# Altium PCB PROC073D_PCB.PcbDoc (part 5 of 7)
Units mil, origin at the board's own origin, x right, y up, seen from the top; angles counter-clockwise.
Board outline 2165.35 x 2695.12 mil, 8 copper layers (Top Layer, L2_GND, L3_SIGNAL 1, L4_SIGNAL 2, L5_SIGNAL 3, L6_SIGNAL 4, L7_GND, Bottom Layer), stack 56.1 mil thick; 414 components, 319 nets, 1353 pads, 1669 vias.
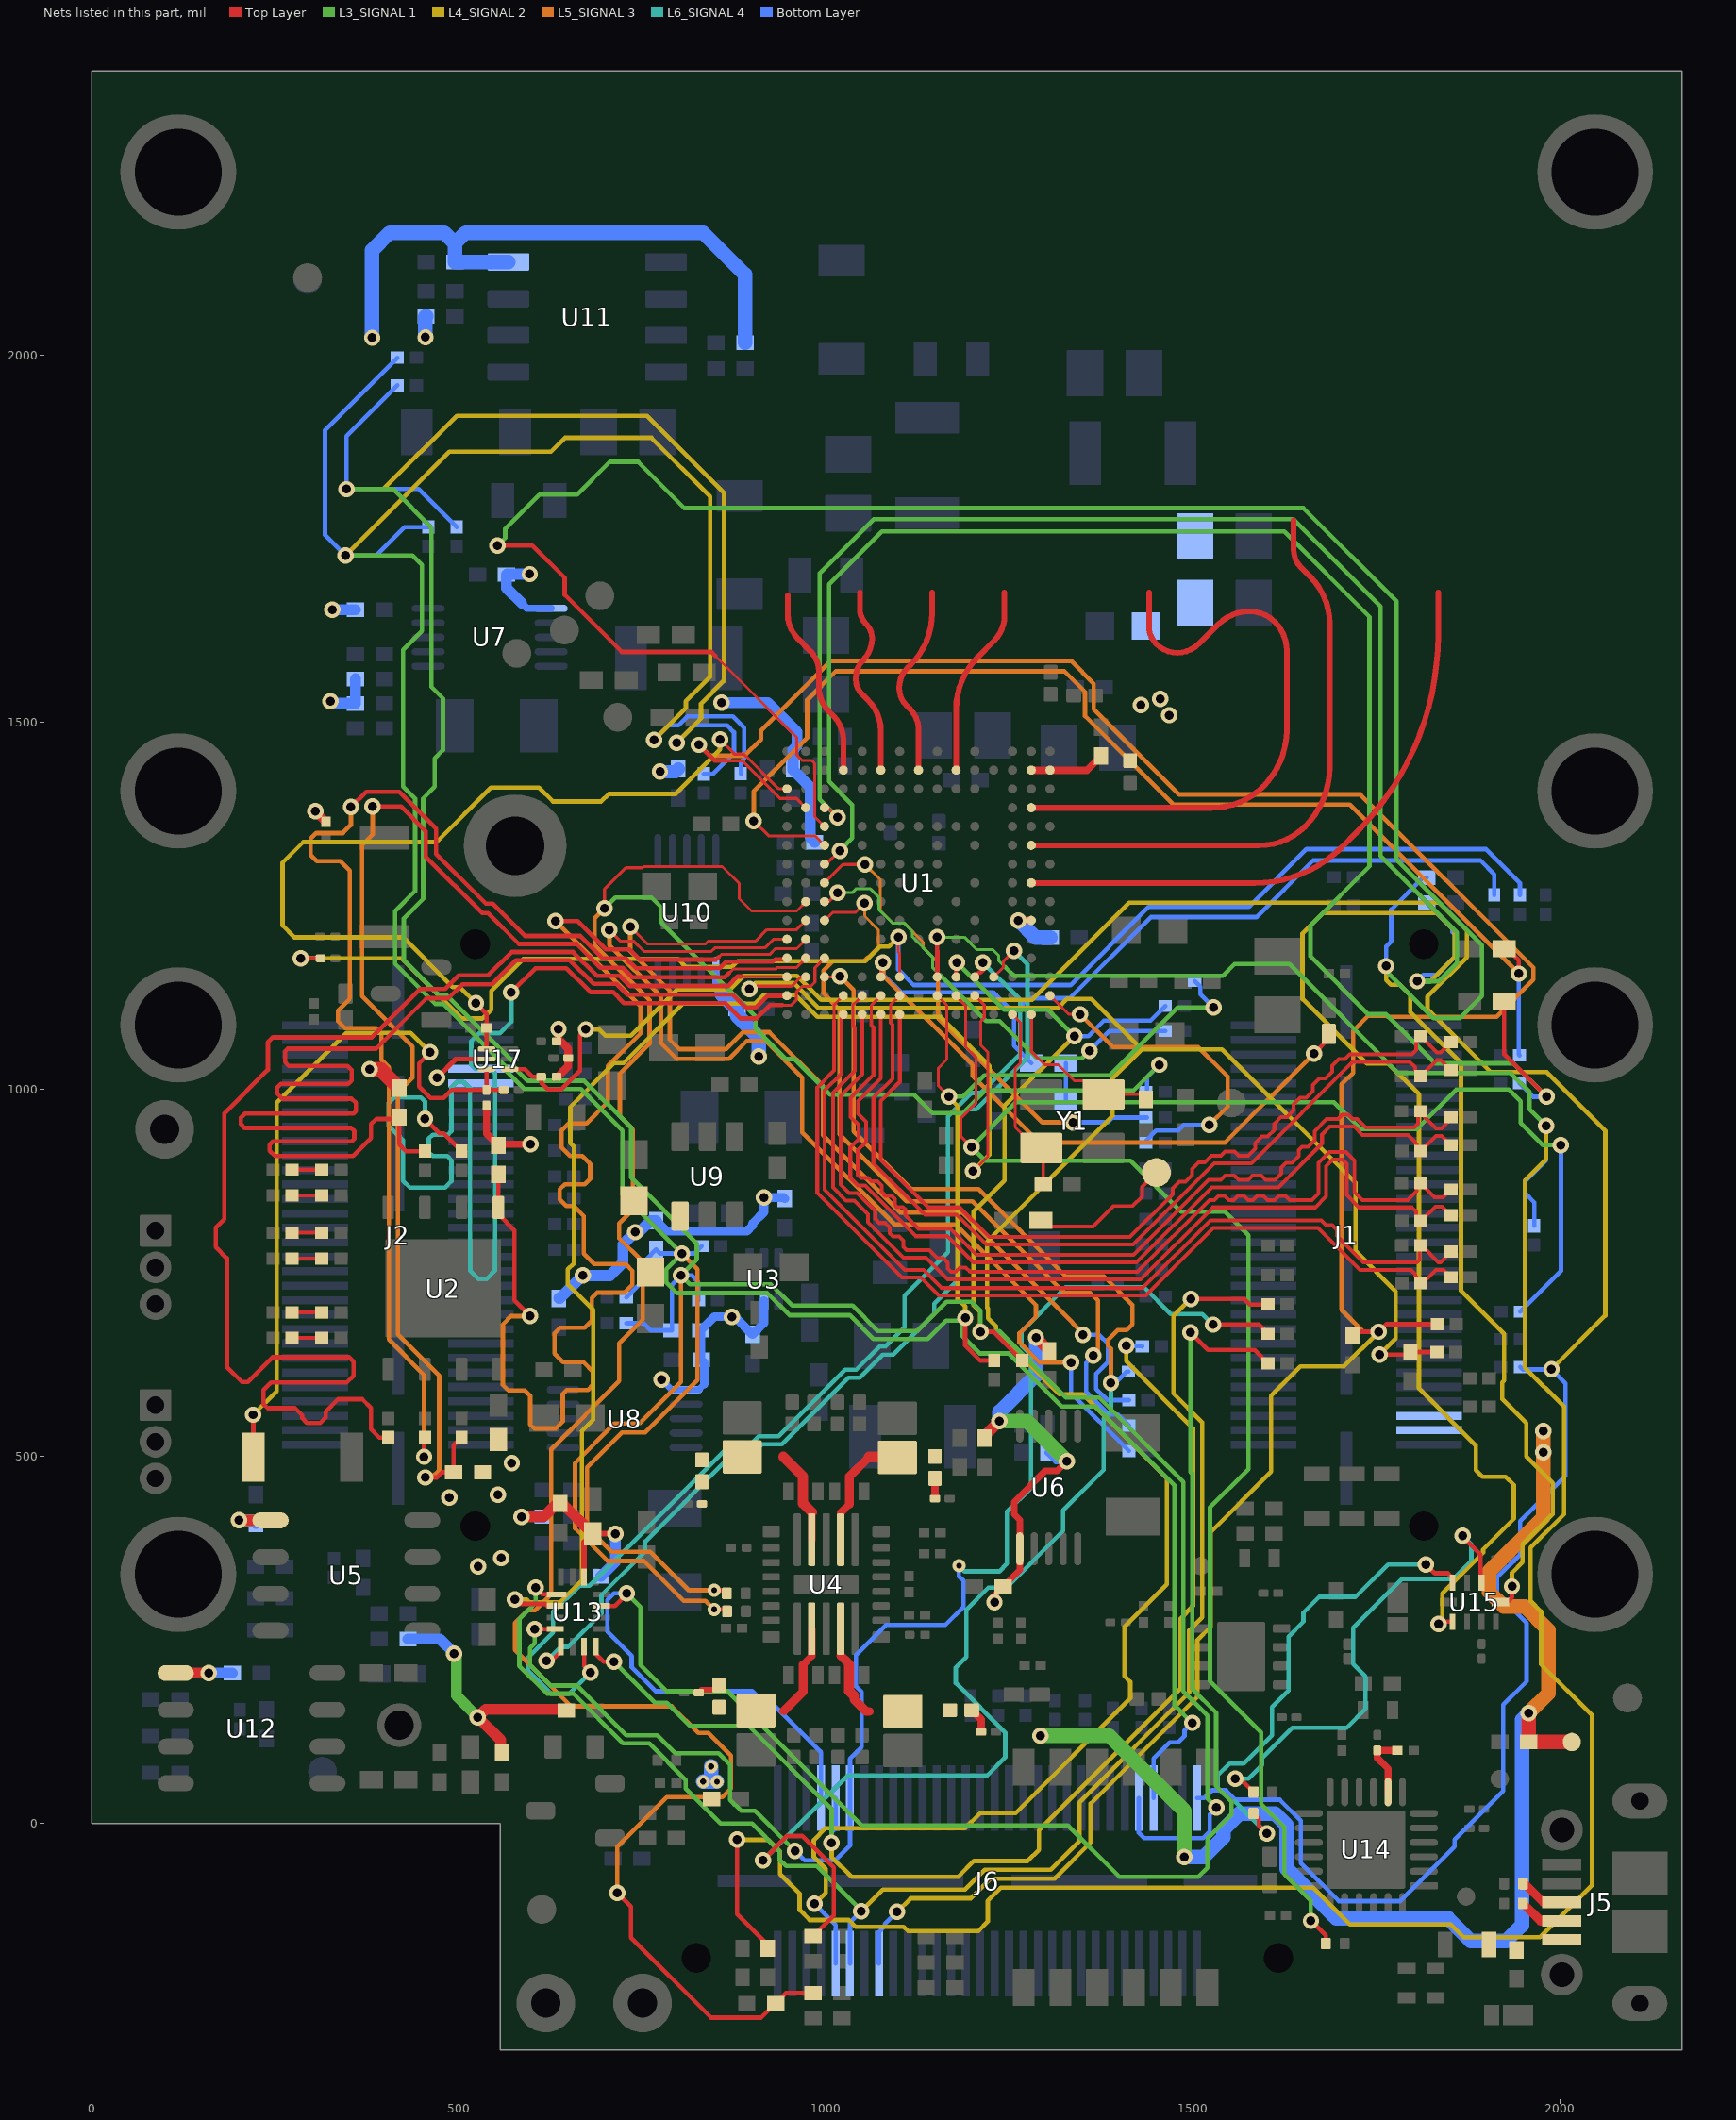
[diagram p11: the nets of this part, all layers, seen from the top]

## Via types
v1: diameter 13.77/15.74 (per signal layer), hole 5.9, Top Layer to L2_GND, tented both sides, 900 vias
v2: diameter 22.4, hole 12.2, Top Layer to Bottom Layer, tented both sides, 509 vias
v3: diameter 13.78/15.75 (per signal layer), hole 5.9, Top Layer to L2_GND, tented both sides, 72 vias
v4: diameter 18, hole 8, Top Layer to Bottom Layer, tented both sides, 71 vias
v5: diameter 22, hole 12.2, Top Layer to Bottom Layer, tented both sides, 57 vias
v6: diameter 25, hole 15, Top Layer to Bottom Layer, tented both sides, 28 vias
v7: diameter 19.68, hole 7.87, Top Layer to Bottom Layer, 16 vias
v8: diameter 13.77/15.74 (per signal layer), hole 5.9, Top Layer to L2_GND, tented top, 15 vias
v9: diameter 13.78/15.75 (per signal layer), hole 5.9, Top Layer to L2_GND, tented top, 1 vias

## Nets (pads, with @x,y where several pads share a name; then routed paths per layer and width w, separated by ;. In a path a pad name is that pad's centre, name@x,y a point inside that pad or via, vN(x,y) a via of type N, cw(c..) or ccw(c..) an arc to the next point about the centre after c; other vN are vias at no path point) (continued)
RADAR_GPIO_1: R66.2 R214.2 U1.J13 | length 2010.4
  Top Layer w4: v2(1098.42,1207.09) 1098.42,1186.89 1100.38,1184.93 U1.J13@1100.39,1153.09
  Top Layer w6: v2(284.89,1178.31) R214.2@311.88,1178.31
  L4_SIGNAL 2 w6: v2(284.89,1178.31) 422.38,1178.31 504.39,1096.29 531.99,1096.29 544.12,1108.41 544.12,1133.77 587.78,1177.43 798.52,1177.43 809.15,1166.81 871.95,1166.81 879.77,1174.63 1053.7,1174.63 1073.32,1194.26 1085.59,1194.26 v2(1098.42,1207.09)
  Bottom Layer w6: v2(1098.42,1207.09) 1098.42,1163 1119.53,1141.9 1332.85,1141.9 1439.38,1248.43 1575.75,1248.43 1654.41,1327.09 1898.61,1327.09 1945,1280.7 R66.2@1945,1264.42
RADAR_GPIO_2: D7.1 R67.2 R185.2 U1.K13 | length 1892.2
  Top Layer w4: U1.K13@1074.8,1153.09 1074.79,1169.37 v2(1077.67,1172.25)
  Top Layer w6: v5(1664.57,1048.61) 1684.74,1068.78 D7.1@1684.74,1075.28
  L5_SIGNAL 3 w6: v2(1077.67,1172.25) 1077.67,1155.22 1199.32,1033.57 1199.32,1018.6 1290.49,927.43 1543.4,927.43 v5(1664.57,1048.61)
  Bottom Layer w6: v2(1077.67,1172.25) 1077.67,1156.76 1102.53,1131.9 1227.96,1131.9 1251.05,1108.8 ; R185.2@1279.5,1035.79 1256,1059.29 1256,1103.86 ; R67.2@1910,1264.42 1910,1292.73 1891.13,1311.6 1663.14,1311.6 1585.97,1234.43 1442.35,1234.43 1331.94,1124.02 1276.17,1124.02 1260.95,1108.8 ; 1251.05,1108.8 1256,1103.86 ; 1251.05,1108.8 1260.95,1108.8 ; 1256,1103.86 1260.95,1108.8
RADAR_HOSTINTR1: J6.10 R10.2 R152.2 U1.P13 | length 3214.1
  Top Layer w4: v2(895.59,1136.43) 899.55,1140.38 953.35,1140.38 965.85,1152.88 U1.P13@972.64,1152.88
  Top Layer w6: v2(1754.07,638.82) 1792.52,638.82 R152.2@1795.94,642.24 R10.2@1831.68,642.24
  L4_SIGNAL 2 w6: v2(895.59,1136.43) 903.79,1144.63 956.23,1144.63 990.39,1110.47 1315.6,1110.47 1328.02,1122.9 1361.41,1122.9 1424.28,1060.03 ; v2(984.35,-109.22) 999.65,-93.92 999.65,-61.63 983.46,-45.44 983.46,-22.05 999.35,-6.16 1189.38,-6.16 1210.26,14.72 1258.62,14.72 1414.33,170.42 1414.33,193.22 1406.72,200.83 1406.72,268.62 1464.29,326.19 1464.29,470.5 1349.84,584.95 1317.77,584.95 1231.45,671.27 1231.45,677.52 1220.64,688.34 1220.64,701.39 1219.49,702.54 1219.49,792.59 1390.36,963.47 1390.36,1014.89 1424.28,1048.81 ; v2(1754.07,638.82) 1775.89,660.63 1775.89,724.97 1721.01,779.85 1721.01,872.87 1539.46,1054.42 1429.89,1054.42 ; 1424.28,1048.81 1429.89,1054.42 ; 1424.28,1048.81 1424.28,1060.03 ; 1424.28,1060.03 1429.89,1054.42
  Bottom Layer w6: v2(984.35,-109.22) 1013.05,-137.91 J6.10@1013.05,-190.65
RADAR_INTn: R184.1 R185.1 | length 51.8
  Bottom Layer w6: R184.1@1326.74,984.02 R185.1@1326.74,1035.79
RADAR_LVDS_0M: R41.2 R230.2 U1.J15 | length 1202.8
  Top Layer w5.2: U1.J15@1100.59,1101.7 1100.59,1010 1074.79,984.2 1074.79,903.5 1139.16,839.13 1182.09,839.13 1222.49,798.73 1413.97,798.73 1472.09,856.85 1472.09,865.1 1481.04,874.06 1489.3,874.06 1498.36,883.12 1498.36,891.38 1507.31,900.33 1515.57,900.33 1524.63,909.39 1537.76,909.39 1543.6,915.23 1556.26,915.23 1562.1,909.39 1574.91,909.39 1584.35,918.82 1584.35,927.08 1593.3,936.03 1601.56,936.03 1610.62,945.1 1610.62,953.35 1619.57,962.3 1627.83,962.3 1636.89,971.37 1636.89,979.62 1645.84,988.58 1654.1,988.58 1663.16,997.64 1663.16,1005.89 1672.11,1014.85 1680.37,1014.85 1689.43,1023.91 1689.43,1032.16 1698.38,1041.12 1706.64,1041.12 1712.84,1047.32 1797.57,1047.32 1803.41,1053.16 1803.41,1065.93 R230.2@1809.84,1072.37 1810.22,1071.98 1832.03,1050.18 1836.91,1050.18 R41.2@1850.8,1064.07
RADAR_LVDS_0P: R39.2 R229.2 U1.J14 | length 1205.6
  Top Layer w4: 1087.88,1094.5 1087.88,1115.01 U1.J14@1100.39,1127.5
  Top Layer w5.2: 1087.88,1094.5 1087.88,1090.49 1090.39,1087.98 1090.39,1014.23 1064.59,988.43 1064.59,899.28 1134.93,828.93 1177.87,828.93 1218.27,788.53 1418.2,788.53 1528.85,899.19 1579.14,899.19 1717.07,1037.12 1794.88,1037.12 1802.06,1029.94 1802.06,1025.66 R229.2@1809.84,1017.88 R229.2@1810.22,1018.26 ; R229.2@1810.26,1018.22 R229.2@1810.22,1018.26 ; R39.2@1850.8,1026.09 1836.91,1039.98 1831.94,1039.98 R229.2@1810.22,1018.26
RADAR_LVDS_1M: R35.2 R228.2 U1.K15 | length 1256
  Top Layer w5.2: U1.K15@1074.8,1101.91 1074.79,1015.13 1043.72,984.06 1043.72,966.45 1054.39,955.79 1054.39,928 1043.35,916.96 1043.35,883.39 1047.68,879.07 1057.31,879.07 1061.69,874.68 1069.95,874.68 1075.8,868.83 1075.8,860.58 1081.18,855.19 1089.44,855.19 1093.96,850.67 1093.96,842.41 1096.69,839.69 1104.94,839.69 1108.01,836.62 1108.01,828.37 1126.21,810.16 1169.48,810.16 1205.01,774.63 1418.72,774.63 1520.99,876.9 1537.51,876.9 1543.35,882.74 1556.01,882.74 1561.84,876.9 1574.66,876.9 1580.5,882.74 1593.16,882.74 1599,876.9 1611.81,876.9 1619.9,884.99 1619.9,893.24 1626.27,899.62 1634.53,899.62 1643.59,908.68 1643.59,916.93 1648.44,921.79 1656.7,921.79 1665.28,930.37 1665.28,942.71 1681.86,959.29 1697.24,959.29 1703.07,965.13 1711.34,965.13 1717.18,959.29 1723.39,959.29 1734.65,948.03 1801.03,948.03 1805.97,952.97 1805.97,966.31 R228.2@1809.84,970.18 1809.84,967.34 1830.33,946.85 1838.34,946.85 1850.8,959.31 R35.2@1850.8,961.88
RADAR_LVDS_1P: R33.2 R227.2 U1.K14 | length 1255.6
  Top Layer w4: 1061.87,1094.5 1061.87,1114.59 U1.K14@1074.8,1127.5
  Top Layer w5.2: 1061.87,1094.5 1061.87,1087.2 1064.59,1084.48 1064.59,1019.35 1033.52,988.28 1033.52,962.23 1044.19,951.56 1044.19,932.23 1033.15,921.19 1033.15,879.17 1043.45,868.87 1053.08,868.87 1121.98,799.96 1165.25,799.96 1200.79,764.43 1422.94,764.43 1525.22,866.7 1616.04,866.7 1675.48,926.14 1675.48,938.48 1686.09,949.09 1719.16,949.09 1730.43,937.83 1792.75,937.83 1802.48,928.09 1802.48,926.6 1805.16,923.92 1805.16,921.14 R227.2@1810.26,916.04 1830.88,936.65 1838.05,936.65 R33.2@1850.8,923.9
RADAR_LVDS_2M: R137.2 R224.2 | length 40.6
  Top Layer w5.2: R137.2@272.99,661.43 R224.2@313.6,661.43
RADAR_LVDS_2P: R136.2 R223.2 | length 40.6
  Top Layer w5.2: R136.2@272.99,696.43 R223.2@313.6,696.43
RADAR_LVDS_3M: R135.2 R222.2 | length 40.6
  Top Layer w5.2: R135.2@272.99,769.68 R222.2@313.6,769.68
RADAR_LVDS_3P: R134.2 R221.2 | length 40.6
  Top Layer w5.2: R134.2@272.99,804.68 R221.2@313.6,804.68
RADAR_LVDS_CLKM: R32.2 R226.2 U1.L15 | length 1337.3
  Top Layer w5.2: U1.L15@1049.41,1101.7 1049.41,1084.28 1049.4,1020.66 1019.78,991.04 1019.78,870.45 1031.58,858.65 1042.55,858.65 1067.21,833.99 1067.21,823.32 1072.61,817.93 1080.86,817.93 1086.71,812.08 1086.71,803.82 1091.1,799.44 1099.35,799.44 1105.2,793.59 1105.2,785.33 1109.59,780.95 1140.54,780.95 1151.67,769.82 1159.93,769.82 1165.77,763.97 1165.77,755.72 1170.16,751.33 1176.36,751.33 1182.2,757.17 1190.47,757.17 1196.31,751.33 1424.27,751.33 1522.26,849.32 1528.8,849.32 1534.64,855.16 1542.91,855.16 1548.75,849.32 1554.95,849.32 1560.79,855.16 1569.06,855.16 1574.89,849.32 1581.1,849.32 1586.94,855.16 1595.61,855.16 1601.45,849.32 1610.84,849.32 1616.68,855.16 1625.64,855.16 1631.48,849.32 1661.78,849.32 1670.6,858.14 1670.6,899.79 1685.54,914.73 1707.71,914.73 1719.51,902.93 1719.51,860.24 1730.42,849.32 1792.01,849.32 1804.09,861.4 1804.09,866.09 R226.2@1809.84,871.84 1828.71,852.97 1840.22,852.97 R32.2@1850.8,863.55
RADAR_LVDS_CLKP: R30.2 R225.2 U1.L14 | length 1347.6
  Top Layer w4: 1036.49,1094.28 1036.49,1114.37 U1.L14@1049.41,1127.29
  Top Layer w5.2: 1036.49,1094.28 1036.49,1086.98 1039.2,1084.27 1039.2,1024.89 1009.58,995.27 1009.58,866.22 1027.35,848.45 1038.33,848.45 1057.01,829.77 1057.01,819.1 1105.36,770.75 1136.32,770.75 1165.93,741.13 1428.49,741.13 1526.49,839.12 1666,839.12 1680.8,853.92 1680.8,895.57 1689.76,904.53 1703.48,904.53 1709.31,898.71 1709.31,856.01 1726.2,839.12 1798.1,839.12 1803.63,833.6 1803.63,827.32 R225.2@1810.26,820.68 1829.86,840.29 1839.06,840.29 R30.2@1850.8,828.55
RADAR_LVDS_FRCLKM: R24.2 R220.2 U1.M15 | length 1259.6
  Top Layer w5.2: U1.M15@1023.82,1101.7 1021.27,1099.16 1021.27,1021.39 998.4,998.51 998.4,862.98 1107.5,753.88 1133.19,753.88 1157.74,729.32 1431.11,729.32 1523.33,821.55 1674.32,821.55 1680.96,814.91 1689.21,814.91 1695.55,808.57 1695.55,800.31 1731.42,764.45 1804.95,764.45 1808.29,767.79 1808.29,785.14 R220.2@1809.84,786.69 ; R220.2@1809.84,787.38 R220.2@1809.84,786.69 ; R24.2@1850.8,779.08 1850.8,778.24 1836.91,764.36 1834.02,764.36 1811.69,786.69 R220.2@1809.84,786.69
RADAR_LVDS_FRCLKP: R22.2 R219.2 U1.M14 | length 1287.2
  Top Layer w4: 1011.07,1093.13 1011.07,1114.96 U1.M14@1023.62,1127.5
  Top Layer w5.2: 1011.07,1093.13 1011.07,1025.61 988.2,1002.74 988.2,858.75 1103.27,743.68 1128.96,743.68 1153.52,719.12 1435.34,719.12 1527.56,811.35 1670.09,811.35 1727.19,754.25 1796.51,754.25 1802.48,748.27 1802.48,746.55 1810.26,738.77 R219.2@1810.26,736.22 1812.79,736.22 1830.59,754.02 1840.86,754.02 R22.2@1850.8,744.08
RADAR_LVDS_VALIDM: R133.2 R218.2 | length 40.6
  Top Layer w5.2: R133.2@272.99,855.5 R218.2@313.6,855.5
RADAR_LVDS_VALIDP: R131.2 R217.2 | length 40.6
  Top Layer w5.2: R131.2@272.99,890.5 R217.2@313.6,890.5
RADAR_MCUCLKOUT: R62.2 U1.N8 | length 671
  Top Layer w4: U1.N8@998.03,1281.05 1007.57,1290.6 1007.57,1290.66 1023.06,1306.15 v2(1053.07,1306.15)
  L5_SIGNAL 3 w4: v2(1053.07,1306.15) 1073.87,1285.35 1073.87,1242.99 1090.58,1226.29 1106.38,1226.29 1132.27,1200.39 1132.27,1193.04 1152.74,1172.57 1152.74,1145.5
  L5_SIGNAL 3 w6: 1152.74,1145.5 1152.74,1096.88 1294.64,954.98 v2(1336.33,954.98)
  Bottom Layer w6: v2(1336.33,954.98) 1383.35,954.98 1389.8,961.43 R62.2@1437.01,961.43
RADAR_MISO1: U1.E14 U13.2 | length 1919.6
  Top Layer w4: v2(1200,888.33) 1220.53,908.87 1220.53,1050.18 1210.95,1059.77 1210.95,1092.72 1215.5,1097.27 1215.5,1114.75 U1.E14@1202.95,1127.29
  Top Layer w6: v2(576.47,305.17) 582.4,299.24 617.96,299.24 620.72,296.48 U13.2@631.29,296.48
  L4_SIGNAL 2 w6: v2(576.47,305.17) 592.29,305.17 596.31,301.15 637.64,301.15 667.49,331 667.49,534.39 682.92,549.81 682.92,699.78 648.54,734.16 648.54,754.79 656.57,762.82 656.57,921.99 651.9,926.66 651.9,976 711.53,1035.63 724.5,1035.63 805.38,1116.5 903.48,1116.5 915.54,1128.56 958.16,1128.56 988.27,1098.44 1156.04,1098.44 1222.47,1032.01 1222.47,910.8 v2(1200,888.33)
RADAR_MOSI1: U1.D13 U13.5 | length 1385
  Top Layer w4: U1.D13@1228.54,1152.88 1241.43,1165.77 1241.43,1173.95 v2(1256.07,1188.6)
  Top Layer w6: v2(619.68,221.88) 626.25,221.88 639.17,234.8 U13.5@639.17,241.36
  L6_SIGNAL 4 w6: v2(619.68,221.88) 620.08,221.88 639.05,240.85 649.15,240.85 694.33,286.03 694.33,311.44 753.44,370.55 753.44,383.98 875.11,505.66 902.23,505.66 913.27,516.7 940.05,516.7 1030.65,607.29 1045.73,607.29 1077.28,638.84 1091.86,638.84 1147.64,694.62 1147.64,707.98 1179.75,740.09 1179.75,958.32 1194.05,972.63 1204.38,972.63 1274.23,1042.48 1274.23,1170.44 v2(1256.07,1188.6)
RADAR_MSS_LOGGER: R31.2 R96.2 U1.F14 | length 2874.4
  Top Layer w4: U1.F14@1177.16,1127.5 1177.15,1126.82 1189.87,1114.1 ; 1190.28,1113.69 1190.28,1057.78 1204.53,1043.53 1204.53,981.7 1183.59,960.75 1183.59,935.92 v2(1197.95,921.56)
  Top Layer w6: v5(1660.15,-132.27) 1660.79,-132.27 1680.69,-152.17 R96.2@1680.69,-163.08
  L3_SIGNAL 1 w6: v5(1660.15,-132.27) 1660.15,-104.5 1623.96,-68.31 1623.96,-4.54 1592.78,26.63 1592.78,124.13 1522.81,194.11 1522.81,430.34 1575.37,482.9 1575.37,801.44 1543.35,833.46 1483.64,833.46 1414.43,902.68 1216.83,902.68 v2(1197.95,921.56) 1258.78,982.39 1691.76,982.39 1728.06,946.09 1804.48,946.09 1858.29,999.91 1929.75,999.91 1946.07,983.59 1946.07,954.12 1976.13,924.06 v2(2000.74,924.06)
  Bottom Layer w6: R31.2@1945.35,697.17 2000.74,752.55 v2(2000.74,924.06)
RADAR_NERR_OUT: R59.2 R169.1 U1.N6 | length 1636.3
  Top Layer w4: v2(901.68,1365.29) 921.88,1345.09 985.16,1345.09 U1.N6@998.23,1332.02
  Top Layer w6: R169.1@1923.62,1191.43 1927.84,1191.43 1943.4,1175.87 v5(1943.4,1157.46)
  L5_SIGNAL 3 w6: v2(901.68,1365.29) 901.68,1405.88 974.47,1478.67 974.47,1530.15 1013.56,1569.25 1324.43,1569.25 1352.77,1540.9 1352.77,1508.13 1473.37,1387.54 1713.33,1387.54 v5(1943.4,1157.46)
  Bottom Layer w6: v5(1943.4,1157.46) 1943.4,1047.24 R59.2@1944.29,1046.36
RADAR_NERRIN: R58.2 R150.1 U1.N7 | length 2319.6
  Top Layer w4: U1.N7@998.03,1306.64 1000.46,1306.64 v2(1018.77,1324.95)
  Top Layer w6: R150.1@1923.62,1119.34 1923.62,1047.64 v2(1981.41,989.85)
  L3_SIGNAL 1 w6: v2(1018.77,1324.95) 1035.84,1342.02 1035.84,1387.27 1004.12,1419 1004.12,1687.54 1076,1759.43 1624,1759.43 1740,1643.43 1740,1303.41 1659.8,1223.21 1659.8,1180.72 1738.4,1102.12 1762.63,1102.12 1829.43,1035.32 1935.94,1035.32 v2(1981.41,989.85)
  Bottom Layer w6: R58.2@1944.29,1008.12 1962.57,989.84 ; 1962.58,989.85 v2(1981.41,989.85)
RADAR_NRST: R171.1 U1.R3 U17.4 | length 1268.6
  Top Layer w4: v2(855.59,1476.43) 875.59,1456.43 888.22,1456.43 935.65,1409 U1.R3@946.84,1409
  Top Layer w6: v2(523.42,1116.99) 537.82,1102.59 R171.1@537.82,1083.65 U17.4@537.82,1054.92
  L4_SIGNAL 2 w6: v2(523.42,1116.99) 501.1,1139.31 491.8,1139.31 424.14,1206.97 276.09,1206.97 260.09,1222.97 260.09,1308.41 288.33,1336.65 469.57,1336.65 543.71,1410.78 609.32,1410.78 628.16,1391.94 694.15,1391.94 704.29,1402.07 794.82,1402.07 855.59,1462.85 v2(855.59,1476.43)
RADAR_NRST_1: J6.59 R42.1 R123.2 U17.1 | length 3578
  Top Layer w6: U17.1@569.32,1027.36 590,1027.36 600.37,1016.99 R123.2@612.21,1016.99 612.21,1008.96 621.65,999.52 639.36,999.52 665,1025.16 665,1073.71 v5(672.99,1081.7)
  L4_SIGNAL 2 w6: v5(672.99,1081.7) 690.74,1081.7 699.62,1072.82 734.38,1072.82 797.6,1136.05 869.47,1136.05 888.05,1154.63 960.37,1154.63 993.19,1121.81 1280.71,1121.81 1412.8,1253.91 1834.46,1253.91 1872.52,1215.84 1872.52,1179.54 1819,1126.02 1819,1109.66 1905.14,1023.53 1981.47,1023.53 2061.12,943.88 2061.12,691.76 v2(1987.95,618.6)
  Bottom Layer w6: J6.59@1505.17,34.94 1514.99,34.94 1525.53,45.48 1544.77,45.48 1557.54,32.71 1617.9,32.71 1646.38,4.23 1646.38,-53.44 1698.3,-105.37 1782.08,-105.37 1856.09,-31.36 1856.09,-21.52 1922.29,44.68 1922.29,162.2 1954.02,193.93 1954.02,273.02 1913.85,313.19 1913.85,335.37 1945.07,366.59 1945.07,411.96 2006.94,473.83 2006.94,599.61 v2(1987.95,618.6) 1948.7,618.6 R42.1@1945.37,621.93
RADAR_NRST_2: C53.1 R165.1 S2.1 U17.6 | length 962.8
  Top Layer w6: S2.1@220.18,498.89 v2(220.18,556.83) ; v2(461.07,1050.23) 446.22,1035.38 446.22,1003.62 461.66,988.18 479.22,988.18 490.14,999.1 R165.1@537.82,999.1 ; U17.6@537.82,1027.36 R165.1@537.82,999.1 ; C53.1@561.55,999.1 R165.1@537.82,999.1
  L4_SIGNAL 2 w6: v2(220.18,556.83) 251.88,588.53 251.88,981.68 346.95,1076.75 434.55,1076.75 v2(461.07,1050.23)
RADAR_OSC_CLKOUT: R61.2 U1.A14 | length 461.2
  Top Layer w4: U1.A14@1305.31,1127.29 1330.44,1102.17 v2(1346,1102.17)
  L5_SIGNAL 3 w6: v2(1346,1102.17) 1390.71,1057.46 1506.77,1057.46 1546.85,1017.38 1546.85,976.28 v2(1522,951.43)
  Bottom Layer w6: R61.2@1435.75,927.14 1435.75,929.85 1449.6,943.7 1479.36,943.7 1487.09,951.43 v2(1522,951.43)
RADAR_PMIC_CLKOUT_SOP2: R63.2 R202.1 R203.1 U1.P9 | length 3525.3
  Top Layer w4: v2(698.56,1246.63) 698.56,1272.61 727.54,1301.6 750.26,1301.6 751.95,1303.29 858.73,1303.29 881.8,1280.22 881.8,1259.55 898.6,1242.75 960.14,1242.75 U1.P9@972.64,1255.25
  Top Layer w6: v2(715.89,-94.12) 734.49,-112.71 734.49,-155.18 843.39,-264.08 911.78,-264.08 R202.1@931.56,-244.3 945.14,-230.73 R203.1@982.36,-230.73
  L3_SIGNAL 1 w6: v2(698.56,1246.63) 713.21,1261.29 762.43,1261.29 776.38,1247.34 776.38,1226.72 904.09,1099.01 904.09,1082.75 945.79,1041.04 957.3,1041.04 1005.57,992.77 1119.89,992.77 1144.9,967.76 1186.5,967.76 1216.88,998.13 1418.44,998.13 v2(1453.74,1033.43)
  L5_SIGNAL 3 w6: v2(698.56,1246.63) 684.97,1233.05 684.97,1196.39 759.72,1121.64 759.72,1061.76 719.42,1021.46 719.42,962.94 737.21,945.15 737.21,836.11 718.55,817.45 718.55,797.06 750.54,765.07 750.54,686.22 718.55,654.22 718.55,602.63 625.82,509.9 625.82,312.59 603.99,290.77 593.96,290.77 576.37,273.17 576.37,236.62 653.19,159.8 789.97,159.8 826.27,123.49 839.98,123.49 870.55,92.92 870.55,47.66 859.27,36.38 783.22,36.38 715.89,-30.95 v2(715.89,-94.12)
  Bottom Layer w6: R63.2@1437.01,996.43 1437.01,1016.7 v2(1453.74,1033.43)
RADAR_QSPI_CS: R50.2 U1.P11 U2.1 | length 1918.3
  Top Layer w4: 853.78,1179.99 857.41,1183.63 923.26,1183.63 931.06,1191.43 960.31,1191.43 U1.P11@972.34,1203.45
  Top Layer w6: R50.2@553.88,884.16 U2.1@553.88,839.09 553.88,829.86 575.82,807.92 575.82,712.58 v2(597.22,691.17) ; v2(631.53,1229.05) 661.97,1229.05 700.59,1190.43 732.63,1190.43 746.28,1176.77 850.55,1176.77 853.78,1179.99
  L5_SIGNAL 3 w6: v2(597.22,691.17) 571.49,691.17 560.03,679.71 560.03,597.72 567.78,589.97 590.05,589.97 597.22,582.8 597.22,543.66 602.57,538.31 632.52,538.31 641.56,547.35 641.56,585.12 647.13,590.68 676.01,590.68 682.71,597.37 682.71,615.51 669.88,628.33 641.99,628.33 630.43,639.89 630.43,667.69 638.14,675.4 671.61,675.4 681.15,684.93 681.15,715.88 688.56,723.3 726.17,723.3 736.44,733.57 736.44,752.77 727.37,761.85 684.47,761.85 670.19,776.12 670.19,827.23 656.47,840.95 646.73,840.95 637.64,850.05 637.64,863.87 644.34,870.57 671.47,870.57 678.98,878.08 678.98,898.42 668.28,909.12 651.58,909.12 639.81,920.88 639.81,943.91 649.48,953.57 673.9,953.57 703,982.67 703,1031.73 747.72,1076.45 747.72,1112.86 v2(631.53,1229.05)
RADAR_QSPI_D0: R45.2 U1.R13 | length 1866
  Top Layer w4: 884.59,1153.63 946.3,1153.63 U1.R13@947.05,1152.88
  Top Layer w6: R45.2@403.88,525.86 391.76,525.86 380.57,537.05 380.57,566.08 368.63,578.03 335.75,578.03 318.83,561.11 318.83,553.03 311.46,545.65 293.36,545.65 286.6,552.41 286.6,556.2 276.96,565.85 239.73,565.85 234.22,571.35 234.22,590.7 244.21,600.69 347.44,600.69 356.65,609.9 356.65,629.2 350.59,635.26 246.66,635.26 212.98,601.58 204.86,601.58 184.2,622.23 184.2,770 169.02,785.18 169.02,811.47 180.88,823.33 180.88,967.19 240.1,1026.41 240.1,1064.12 246.71,1070.74 381.54,1070.74 447.24,1136.44 481.53,1136.44 500.21,1155.12 540.01,1155.12 571.74,1186.85 655.7,1186.85 688.12,1154.43 719.13,1154.43 732.93,1140.63 866.71,1140.63 879.71,1153.63 884.59,1153.63
RADAR_QSPI_D1: R46.1 U1.N12 | length 1798.5
  Top Layer w4: 940.59,1114.5 952.87,1114.5 959.37,1121 959.37,1132.2 967.27,1140.1 979.17,1140.1 984.97,1145.9 984.97,1165.64 U1.N12@998.03,1178.68
  Top Layer w6: v2(454.04,959.8) 473.8,940.04 479.59,940.04 R46.1@503.88,915.75 ; v2(571.53,1131.91) 604.47,1164.85 646.59,1164.85 679.01,1132.43 710.02,1132.43 725.05,1117.4 862.77,1117.4 883.74,1096.43 905.59,1096.43 923.66,1114.5 940.59,1114.5
  L6_SIGNAL 4 w6: v2(454.04,959.8) 454.04,983.65 448.76,988.93 411.87,988.93 404.24,981.31 404.24,950.35 423.82,930.77 423.82,875.72 433.52,866.01 481.14,866.01 489.94,874.81 489.94,903.39 484.31,909.02 464.79,909.02 459.17,914.63 459.17,932.85 464.56,938.23 485.25,938.23 489.94,942.92 489.94,1002.64 497.25,1009.95 506.62,1009.95 515.22,1001.35 515.22,753.2 526.13,742.29 538.3,742.29 549.52,753.51 549.52,1021.58 543.32,1027.78 523.2,1027.78 517.11,1033.87 517.11,1066.04 527.5,1076.43 556.07,1076.43 571.53,1091.89 v2(571.53,1131.91)
RADAR_QSPI_D2: R44.1 R47.1 U1.R14 | length 1883.7
  Top Layer w6: R47.1@453.88,915.75 428.25,915.75 418.88,925.12 R44.1@418.88,962.2 416.23,959.55 387.54,959.55 380.67,952.67 380.67,933.56 356.05,908.94 249.95,908.94 242.53,916.37 242.53,924.76 246.89,929.12 354.34,929.12 357.79,932.57 357.79,942.95 353.44,947.29 208.53,947.29 203.23,952.59 203.23,961.4 208.81,966.98 356.56,966.98 359.95,970.36 359.95,981.48 354.29,987.14 259.65,987.14 252.5,994.29 252.5,1002.11 257.85,1007.45 349.75,1007.45 354.21,1011.91 354.21,1026.27 348.59,1031.88 268.42,1031.88 263.51,1036.8 263.51,1051.69 267.11,1055.29 387.32,1055.29 456.03,1124 486.06,1124 505.18,1143.12 544.98,1143.12 577.71,1175.85 651.14,1175.85 683.57,1143.43 714.57,1143.43 729.37,1128.63 873.39,1128.63 890.59,1111.43 904.72,1111.43 920.59,1127.29 U1.R14@947.05,1127.29
RADAR_QSPI_D3: R49.1 R51.2 U1.P12 | length 1803.8
  Top Layer w4: 868.06,1158.13 873.56,1163.63 931.63,1163.63 933.98,1165.97 960.14,1165.97 U1.P12@972.64,1178.47
  Top Layer w6: v2(382.73,1385) 421.39,1385 455.08,1351.31 455.08,1316.54 531.88,1239.75 540.01,1239.75 581.9,1197.85 660.26,1197.85 692.68,1165.43 723.68,1165.43 736.48,1152.63 862.56,1152.63 868.06,1158.13 ; v5(454.33,471.43) 470.55,471.43 477.63,478.51 R49.1@493.13,478.51 493.13,515.11 R51.2@503.88,525.86
  L5_SIGNAL 3 w6: v2(382.73,1385) 382.73,1346.72 368.49,1332.47 368.49,1127.11 437.22,1058.38 437.22,1015.55 416.95,995.29 416.95,666.19 473.42,609.72 473.42,481.36 463.5,471.43 v5(454.33,471.43)
RADAR_QSPI_SCLK: R48.2 U1.R12 | length 1804.8
  Top Layer w4: U1.R12@945.56,1176.99 U1.R12@947.05,1178.47
  Top Layer w6: v2(353.19,1384.32) 374.07,1405.2 418.86,1405.2 469.38,1354.68 469.38,1320.19 536.95,1252.62 546.14,1252.62 589.91,1208.85 665.35,1208.85 695.77,1178.43 727.66,1178.43 741.31,1164.77 855.27,1164.77 864.13,1173.63 927.49,1173.63 930.85,1176.99 U1.R12@945.56,1176.99 ; v5(452.72,499.43) 452.72,524.7 R48.2@453.88,525.86
  L5_SIGNAL 3 w6: v2(353.19,1384.32) 353.19,1359.84 342.24,1348.89 305.97,1348.89 298.39,1341.31 298.39,1318.97 306.82,1310.54 338.76,1310.54 351.72,1297.58 351.72,1123.32 335.38,1106.98 335.38,1093.03 345.24,1083.18 387.67,1083.18 394.65,1076.2 394.65,1039.95 404.76,1029.84 404.76,659.12 452.72,611.15 v5(452.72,499.43)
RADAR_RS232RX: R154.1 U1.N4 U15.6 | length 3451.1
  Top Layer w4: U1.N4@998.03,1383.41 1002.76,1383.41 v2(1015.87,1370.3)
  Top Layer w6: v2(1833.86,271.75) 1837.17,275.06 U15.6@1853.23,275.06 U15.6@1853.23,268.33
  L3_SIGNAL 1 w6: v2(1015.87,1370.3) 991.26,1394.91 991.26,1702.69 1065,1776.43 1636.12,1776.43 1755,1657.55 1755,1317.6 1859.03,1213.58 1859.03,1171.67 1834.58,1147.22 v5(1804.96,1147.22)
  L4_SIGNAL 2 w6: v5(1804.96,1147.22) 1823.23,1147.22 1856.17,1180.16 1856.17,1215.22 1831.39,1240 1676.81,1240 1648.92,1212.11 1648.92,1122.77 1736.38,1035.3 1765.32,1035.3 1807.52,993.1 1807.52,592.39 1884.93,514.98 1884.93,481.44 1893.86,472.52 1925.39,472.52 1936.57,461.34 1936.57,415.17 1894.8,373.4 1894.8,368.85 1839.45,313.5 1839.45,277.35 v2(1833.86,271.75)
  Bottom Layer w6: v5(1804.96,1147.22) 1813.12,1155.38 1831.39,1155.38 1856.17,1180.16 1856.17,1210.75 1852.95,1213.97 1852.95,1218.44 1818.2,1253.19 R154.1@1818.2,1254.19
RADAR_RS232TX: R153.1 U1.N5 U15.10 | length 3943.6
  Top Layer w4: 849.01,1590.33 960.14,1479.21 960.14,1455.08 967.34,1447.88 980.33,1447.88 984.73,1443.48 984.73,1371.11 U1.N5@998.03,1357.82
  Top Layer w6: v2(552.79,1740.44) 600.36,1740.44 644.23,1696.56 644.23,1673.26 721.9,1595.59 843.76,1595.59 849.01,1590.33 ; U15.10@1918.19,301.64 1927.34,301.64 1934.05,308.35 v2(1934.05,323.04)
  L3_SIGNAL 1 w6: v2(552.79,1740.44) 563.31,1750.96 563.31,1763.35 609.78,1809.82 661.23,1809.82 705.75,1854.35 744.3,1854.35 807.22,1791.43 1650,1791.43 1777,1664.43 1777,1312.58 1893.15,1196.43 1893.15,1127.07 1863.01,1096.93 1826.97,1096.93 1762.69,1161.21 v5(1762.69,1167.87)
  L4_SIGNAL 2 w6: v5(1762.69,1167.87) 1762.69,1148.83 1769.41,1142.11 1781.79,1142.11 1795.46,1128.44 1795.46,1104.85 1864.71,1035.59 1864.71,725.62 1923.4,666.94 1923.4,603.21 1920.8,600.62 1920.8,578.09 1953.59,545.3 1953.59,499.86 1989.44,464.01 1989.44,421.37 1948.5,380.44 1948.5,356.1 1934.05,341.65 v2(1934.05,323.04)
  Bottom Layer w6: v5(1762.69,1167.87) 1762.69,1194.59 1769.67,1201.58 1769.67,1244.78 1813.02,1288.13 R153.1@1818.2,1288.13
RADAR_SCL: J6.53 R25.2 R37.1 R53.1 R56.1 R108.2 R109.2 R143.2 R159.2 R181.1 U1.G14 | length 6111.5
  Top Layer w4: U1.G14@1151.57,1127.5 1164.57,1114.5 1164.57,1040.44 1152.89,1028.76 1152.89,1004.89 v2(1167.54,990.24)
  Top Layer w6: v4(847.84,317.82) 860.84,317.82 R181.1@865.01,313.66 ; v5(1189.64,688.55) 1189.64,650.74 1209.66,630.72 R25.2@1229.01,630.72
  L3_SIGNAL 1 w6: v2(345.81,1726.85) 437.15,1726.85 449.83,1714.17 449.83,1624.04 424,1598.21 424,1412.31 440.5,1395.82 440.5,1269.8 413.27,1242.57 413.27,1170.9 467.89,1116.27 478.6,1116.27 564.32,1030.55 564.32,1025.24 589.04,1000.52 666.29,1000.52 722.84,943.97 722.84,857.33 v2(803.74,776.43) 803.74,776 782.54,754.8 782.54,736.73 796.73,722.54 919.97,722.54 950.11,692.4 1032.33,692.4 1064.83,659.9 1138.39,659.9 1163.64,685.15 v5@1185.29,685.15 ; v2(1167.54,990.24) 1186.59,990.24 1215.46,1019.11 1386.68,1019.11 1479,1111.43 v2(1528,1111.43) ; v5(1189.64,688.55) 1188.69,688.55 v5@1185.29,685.15 ; v2@1498.5,136.89 1474.81,160.57 1474.81,460.4 1366.98,568.23 1320.77,568.23 1248.59,640.41 1209.15,640.41 1185.29,664.27 v5@1185.29,685.15
  L5_SIGNAL 3 w6: v2(803.74,776.43) 825.07,755.1 825.07,603.99 753.97,532.89 722.25,532.89 674.72,485.36 674.72,403.98 708.32,370.39 760.81,370.39 813.37,317.82 v4(847.84,317.82)
  L4_SIGNAL 2 w6: v2(345.81,1726.85) 487.22,1868.26 625.61,1868.26 644.38,1887.03 762.38,1887.03 842.5,1806.91 842.5,1561.52 809.24,1528.25 809.24,1518.9 v2(765.92,1475.58) ; v2(1167.54,990.24) 1167.54,988.84 1179.29,977.09 1179.29,714.32 1189.64,703.97 v5(1189.64,688.55)
  Bottom Layer w6: R159.2@416.41,1996.15 317.99,1897.72 317.99,1754.67 v2(345.81,1726.85) 387.71,1726.85 426.36,1765.49 R108.2@458.56,1765.49 ; R109.2@727.99,716.43 755.45,743.89 755.45,768.46 R53.1@768.74,781.74 774.06,776.43 v2(803.74,776.43) 820.75,776.43 R56.1@830.75,786.43 ; v2(765.92,1475.58) 785.74,1495.4 799.24,1495.4 811.52,1507.68 873.29,1507.68 888.74,1492.23 888.74,1449.95 883.92,1445.13 R143.2@883.92,1429.6 ; J6.53@1446.12,34.94 1446.12,88.78 1468,110.66 1479.55,110.66 1488.13,119.25 1488.13,126.64 1498.38,136.89 v2@1498.5,136.89 ; R37.1@1502.01,1147.43 1509.94,1139.5 1509.94,1129.49 v2(1528,1111.43)
  other v2: 1498.9,137.38
RADAR_SDA: J6.51 R29.2 R34.1 R52.1 R55.1 R110.2 R111.2 R144.2 R160.2 R180.1 U1.F13 | length 6166.4
  Top Layer w6: v4(847.84,291.76) 847.94,291.66 862.85,291.66 R180.1@865.35,289.16 ; U1.F13@1177.16,1153.09 1177.15,1170.85 v2(1178.55,1172.25) ; v5(1210.46,669.78) 1228.12,669.78 R29.2@1267.18,630.72
  L3_SIGNAL 1 w6: v5(347.1,1817.27) 410.43,1817.27 462.79,1764.91 462.79,1547.96 478.49,1532.26 478.49,1461.98 467.3,1450.79 467.3,1412.02 451.5,1396.21 451.5,1259.05 425.27,1232.82 425.27,1175.87 472.81,1128.33 483.52,1128.33 575.32,1036.52 575.32,1029.8 593.6,1011.52 670.84,1011.52 734.84,947.52 734.84,879.69 824.01,790.52 824.01,767.7 v2(802.74,746.43) 814.63,734.54 924.94,734.54 954.11,705.37 1036.12,705.37 1070.59,670.9 1124.17,670.9 1164.11,710.84 1198.12,710.84 1210.46,698.5 v5(1210.46,669.78) 1235.06,669.78 1236,670.72 1326.49,580.23 1371.95,580.23 1486.81,465.37 1486.81,179.93 1519.25,147.5 1519.25,34.46 v2(1531.74,21.97) ; v2(1178.55,1172.25) 1242.71,1108.09 1302.34,1108.09 v2(1338,1072.43)
  L5_SIGNAL 3 w6: v2(802.74,746.43) 802.74,601.64 745.99,544.89 712.22,544.89 658.37,491.03 658.37,402.05 702.68,357.74 751.95,357.74 806.1,303.59 836,303.59 v4(847.84,291.76)
  L4_SIGNAL 2 w6: v5(347.1,1817.27) 397.49,1817.27 497.36,1917.14 756.2,1917.14 861.21,1812.14 861.21,1556.36 829.89,1525.05 829.89,1505.06 v2(796.68,1471.84) ; 1200.61,708.55 1200.61,833.36 1243.17,875.92 1243.17,977.59 v2(1338,1072.43) ; 1200.64,708.52 1200.64,705.84 1209.64,696.84 1209.64,680.27 1207.49,678.12 1207.49,672.75 v5(1210.46,669.78)
  Bottom Layer w6: R160.2@416.41,1958.61 347.1,1889.29 v5(347.1,1817.27) 445.38,1817.27 R110.2@497.17,1765.49 ; R111.2@727.99,681.43 751.86,681.43 761.52,671.77 R52.1@790.25,671.77 790.25,733.93 v2(802.74,746.43) 817.12,746.43 826.49,737.06 R55.1@826.49,712.79 ; v2(796.68,1471.84) 820.52,1495.68 865.3,1495.68 874.74,1486.24 874.74,1457.81 846.35,1429.42 R144.2@833.74,1429.42 ; v2(1338,1072.43) 1357.42,1072.43 1378.42,1093.43 1442.01,1093.43 R34.1@1462.01,1113.43 ; J6.51@1426.43,34.94 1426.01,34.52 1426.01,-12.42 1433.26,-19.66 1513.51,-19.66 1522.5,-10.68 1522.5,12.72 v2(1531.74,21.97)
RADAR_SPICLK1: U1.E13 U13.7 | length 1497.8
  Top Layer w6: U13.7@670.66,241.36 670.66,214.49 v2(679.28,205.87) ; U1.E13@1202.75,1153.09 1208.65,1159 1210.37,1159 1213.87,1162.51 v2(1213.87,1172.5)
  L6_SIGNAL 4 w6: v2(679.28,205.87) 649.62,176.21 626.74,176.21 594.61,208.35 594.61,226.54 628.47,260.41 628.47,288.38 664.17,324.08 677.97,324.08 870.56,516.66 897.67,516.66 908.71,527.7 935.5,527.7 1026.09,618.29 1041.18,618.29 1072.72,649.84 1080.94,649.84 1106.82,675.72 1106.82,719.02 1166.01,778.21 1166.01,962.97 1198.05,995.01 1211.2,995.01 1264.23,1048.04 1264.23,1122.14 v2(1213.87,1172.5)
RADAR_SYNC_IN: J6.16 R36.2 R155.2 U1.P4 | length 3717
  Top Layer w4: 865.59,1447.43 885.9,1447.43 937.33,1396 959.84,1396 U1.P4@972.44,1383.41
  Top Layer w6: v2(827.01,1468.96) 848.54,1447.43 865.59,1447.43 ; R155.2@1717.01,664.28 1717.82,664.28 1723.38,669.84 v2(1752.62,669.84) 1762.83,680.05 R36.2@1832.36,680.05
  L5_SIGNAL 3 w6: v2(827.01,1468.96) 841.7,1454.26 889.45,1454.26 911.79,1476.6 911.79,1488.52 1006.6,1583.33 1333.65,1583.33 1364.71,1552.26 1364.71,1517.63 1480.92,1401.43 1727.72,1401.43 1963.4,1165.75 1963.4,1149.18 1912.93,1098.71 1764.81,1098.71 1763.28,1100.24 1738.62,1100.24 1717.81,1079.43 1717.81,1022.46 1701.85,1006.5 1701.85,699.72 1731.73,669.84 v2(1752.62,669.84)
  L4_SIGNAL 2 w6: v2(1096.61,-120.1) 1115.08,-101.63 1197.21,-101.63 1224.09,-74.75 1311.05,-74.75 1360.39,-25.42 1360.39,27.46 1505.66,172.73 1505.66,249.87 1523.54,267.75 1523.54,396.81 1606.14,479.41 1606.14,582.89 1645.78,622.52 1705.3,622.52 v2(1752.62,669.84)
  Bottom Layer w6: J6.16@1072.1,-190.65 1072.1,-147.43 1080.28,-139.26 1080.28,-136.43 v2(1096.61,-120.1)
RADAR_SYNC_OUT_SOP1: R16.2 R206.1 U1.G13 | length 3805.4
  Top Layer w6: v2(878.98,-21.81) 878.98,-123.1 920.56,-164.68 R206.1@920.56,-169.67 ; v2(1151.47,1207.05) 1151.47,1188.85 1151.56,1188.76 U1.G13@1151.57,1153.09
  L3_SIGNAL 1 w4: v2(1151.47,1207.05) 1188.38,1207.05 1205.21,1190.21 1227.21,1190.21 1235,1182.43 1235,1175.43 1244.04,1166.39
  L3_SIGNAL 1 w6: 1244.04,1166.39 1256,1154.43 1540.31,1154.43 1556.33,1170.45 1631.01,1170.45 1779.18,1022.28 1932.01,1022.28 1958.07,996.22 1958.07,972.93 v2(1980.54,950.46)
  L4_SIGNAL 2 w6: v2(878.98,-21.81) 921.43,-21.81 937.47,-37.85 937.47,-68.55 964.15,-95.23 964.15,-117.58 977.66,-131.09 1030.94,-131.09 1040.15,-140.3 1105.86,-140.3 1111.82,-146.26 1207.56,-146.26 1220.31,-133.51 1220.31,-104.98 1238.01,-87.28 1663.4,-87.28 1713.38,-137.26 1850.61,-137.26 1868.02,-154.66 1972.44,-154.66 2043.05,-84.05 2043.05,147.7 1973.83,216.92 1973.83,288.87 1959.5,303.19 1959.5,375.88 2004.9,421.28 2004.9,567.96 1951.84,621.02 1951.84,875.75 1980.54,904.45 v2(1980.54,950.46)
  Bottom Layer w6: R16.2@1964.4,814.13 1964.4,845.89 1952.1,858.19 1952.1,874.93 1980.54,903.37 v2(1980.54,950.46)
RADAR_TCK: R6.2 U1.P10 | length 1385.5
  Top Layer w4: v2(733.57,1221.41) 757.22,1197.77 835.53,1197.77 839.39,1201.63 903.92,1201.63 919.59,1217.3 959.93,1217.3 U1.P10@972.44,1229.86 U1.P10@972.44,1229.86
  L5_SIGNAL 3 w6: v2(733.57,1221.41) 733.57,1188.09 787.47,1134.19 787.47,1067.5 800.41,1054.56 863.47,1054.56 886.56,1077.66 922.98,1077.66 995.76,1004.88 995.76,937.34 1101.2,831.9 1185.97,831.9 1329.8,688.07 1341.63,676.23 1350.08,667.79 v2(1350.08,665.68)
  Bottom Layer w6: v2(1350.08,665.68) 1371.88,665.68 1384.26,653.3 1384.26,629.08 1367.8,612.62 1367.8,592.06 1383.02,576.84 R6.2@1412.44,576.84
RADAR_TDI: R5.1 U1.R11 | length 1460.5
  Top Layer w4: v2(705.17,1216.68) 720.42,1201.43 738.37,1201.43 752.03,1187.77 843.97,1187.77 848.83,1192.63 916.79,1192.63 928.23,1204.07 U1.R11@947.05,1204.07
  L5_SIGNAL 3 w6: v2(705.17,1216.68) 705.17,1196.34 775.47,1126.04 775.47,1062.53 796.48,1041.52 868,1041.52 892.14,1065.66 918.01,1065.66 967.74,1015.92 967.74,941.23 1093.24,815.73 1176.17,815.73 1285.93,705.98 1285.93,690.28 1263.52,667.87 1263.52,655.17 1290.57,628.12 v2(1333.9,628.12)
  Bottom Layer w6: v2(1333.9,628.12) 1333.9,586.09 R5.1@1412.44,507.55
RADAR_TDO_SOP0: R4.2 R209.1 U1.N13 | length 2138
  Top Layer w4: U1.N13@998.03,1153.09 1018.12,1153.1 v2(1018.89,1153.86)
  Top Layer w6: v2(914.26,-49.73) 947.27,-16.72 967.82,-16.72 1010.48,-59.38 1010.48,-124.81 R209.1@982.36,-152.92 ; R209.1@982.36,-153.92 R209.1@982.86,-153.42
  L5_SIGNAL 3 w6: v2(1018.89,1153.86) 1037.5,1135.26 1037.5,942.72 1116.01,864.21 1207.75,864.21 1326.96,745 1378.9,745 1417.45,706.45 1417.45,680.1 1409.59,672.24 1397.09,672.24 1384.25,659.4 1384.25,650.48 1388,646.73 v2(1388,600.43)
  L6_SIGNAL 4 w6: v2(914.26,-49.73) 1029.81,65.82 1219.75,65.82 1244.09,90.15 1244.09,124.09 1176.75,191.43 1176.75,212.57 1190.97,226.8 1190.97,291.47 1221.03,321.52 1245.55,321.52 1322.82,398.8 1322.82,426.56 1377.94,481.67 1377.94,551.72 1388,561.78 v2(1388,600.43)
  Bottom Layer w6: v2(1388,600.43) 1394.19,600.43 1409.39,615.63 R4.2@1411.98,615.63
RADAR_TMS: R8.2 U1.N10 | length 1106
  Top Layer w4: U1.N10@998.03,1229.86 1008.97,1240.82 1039.8,1240.82 v2(1052.67,1253.69)
  L5_SIGNAL 3 w4.02: v2(1052.67,1253.69) 1052.67,1235.75 1071.23,1217.19 1071.23,1193.92 1056.74,1179.43
  L5_SIGNAL 3 w6: 1056.74,1179.43 1051.95,1174.63 1009.66,1174.63 996.42,1161.39 996.42,1130.53 1018.49,1108.47 1018.49,938.52 1109.54,847.47 1199.58,847.47 1324.52,722.53 1360.12,722.53 1370.28,712.36 1370.28,643.67 v2(1364.06,637.45)
  Bottom Layer w6: v2(1364.06,637.45) 1354.1,627.49 1354.1,588.26 1385.26,557.1 1397.53,557.1 R8.2@1412.44,542.19
RADAR_VBGAP: C6.1 U1.B10 | length 70.4
  Top Layer w10: v2(1262.07,1229.87) U1.B10@1279.52,1229.86
  Bottom Layer w20: v2(1262.07,1229.87) 1285.51,1206.43 C6.1@1305.32,1206.43
RADAR_VOUT_PA: C4.2 C7.2 C8.2 C102.1 R1.2 U1.A2 U1.B2 | length 102.2
  Top Layer w10: U1.B2@1279.72,1434.38 1355.41,1434.38 C4.2@1374.18,1453.15
  other v2: 1467.38,1509.38 1428.8,1523.15 1455.24,1531.79
RADAR_VSENSE: R77.1 TP7.1 | length 199.3
  Top Layer w5: R77.1@1292.37,821.43 1300.89,812.91 1363.55,812.91 1391.77,841.13 1417.81,841.13 1430.46,853.78 1430.46,866.89 TP7.1@1450,886.43
RADAR_WARMRST: R64.2 U1.N9 | length 604.6
  Top Layer w4: U1.N9@998.03,1255.45 1003.79,1255.46 v2(1016.02,1267.69)
  L3_SIGNAL 1 w4: v2(1016.02,1267.69) 1035.72,1267.69 1040.92,1272.89 1060.63,1272.89 1071.87,1261.64 1071.87,1244.99 1090.58,1226.29 1106.38,1226.29 1117.62,1215.04 1117.62,1207.69 1145.07,1180.24 1145.07,1166.09 1155.24,1155.93
  L3_SIGNAL 1 w6: 1155.24,1155.93 1218.15,1093.01 1236.41,1093.01 1287.29,1042.13 1348.44,1042.13 v2(1358.74,1052.43)
  Bottom Layer w6: v2(1358.74,1052.43) 1385.74,1079.43 R64.2@1462.01,1079.43
RADAR_XTALM: C33.2 U1.C15 Y1.1 | length 257.7
  Top Layer w4: U1.C15@1253.93,1101.91 1264.57,1091.27 1264.57,1035.41 1257.72,1028.56 1257.72,948.43 1286.14,920.01 Y1.1@1293.27,920.01 1295.91,917.37 C33.2@1295.91,871.43
RADAR_XTALP: C32.2 U1.B15 Y1.3 | length 233.3
  Top Layer w4: U1.B15@1279.72,1101.7 1279.72,1051.29 1297.59,1033.43 1316.59,1033.43 1338.59,1011.43 1359.33,1011.43 Y1.3@1377.91,992.85 1428.86,992.84 C32.2@1435.59,986.11
RX1: U1.M2 | length 261.6
  Top Layer w7.79: 947.77,1672.61 947.77,1647.57 ccw(c995.92,1647.57) 961.87,1613.52 978.76,1596.63 cw(c951.21,1569.08) 990.17,1569.08 990.17,1548.65 ccw(c1039.3,1548.65) 1004.54,1513.93 1009.93,1508.54 cw(c976.89,1475.5) 1023.62,1475.5 U1.M2@1023.62,1434.59
RX2: U1.K2 | length 262.5
  Top Layer w7.79: 1046.2,1676.38 1046.2,1653.97 ccw(c1075.16,1653.97) 1054.68,1633.49 cw(c1035.22,1614.03) 1062.74,1614.03 cw(c1020.25,1614.03) 1050.29,1583.98 ccw(c1073.36,1560.92) 1040.74,1560.92 1040.74,1557.74 ccw(c1068.05,1557.74) 1048.73,1538.44 1057.06,1530.11 ; 1057.07,1530.1 cw(c1014.23,1487.28) 1074.8,1487.28 U1.K2@1074.8,1434.59
RX3: U1.H2 | length 262.2
  Top Layer w7.79: U1.H2@1125.98,1434.59 1125.98,1493.58 1125.74,1493.82 ccw(c1085.51,1489.43) 1114.13,1518.04 1109.64,1522.53 cw(c1133.54,1546.43) 1099.74,1546.43 cw(c1138.37,1546.43) 1111.05,1573.74 1115.34,1578.02 ccw(c1044.63,1648.73) 1144.63,1648.73 1144.63,1676.38
RX4: U1.F2 | length 262.7
  Top Layer w7.79: U1.F2@1177.16,1434.59 1177.16,1517.43 cw(c1277.16,1517.43) 1206.45,1588.14 1228.74,1610.43 ccw(c1194.2,1644.97) 1243.05,1644.97 1243.05,1676.38
SPI_CLK1: J6.9 R9.1 U13.8 | length 1689.9
  Top Layer w6: U13.8@686.41,241.36 686.41,231.4 697.41,220.4 v2(711.43,220.4)
  L3_SIGNAL 1 w6: v2(711.43,220.4) 767.24,164.59 783.14,164.59 814.82,132.91 894.76,132.91 1007.72,19.94 v2(1007.72,-26.36)
  L4_SIGNAL 2 w6: v2(1007.72,-26.36) 1007.72,-45.31 1034.87,-72.46 1179.89,-72.46 1201.6,-50.75 1274.82,-50.75 1289.97,-35.61 1289.97,-9.01 1482.8,183.81 1482.8,279.28 1500.29,296.77 1500.29,538.14 1408.77,629.66 v2(1408.77,650.67)
  Bottom Layer w6: v2(1007.72,-26.36) 1007.72,-11.86 1013.05,-6.53 J6.9@1013.05,34.94 ; v2(1408.77,650.67) 1430.08,650.67 R9.1@1430.75,650
SPI_CS1: J6.7 R7.1 U13.11 | length 2436.4
  Top Layer w6: U13.11@694.28,296.48 712.54,296.48 v2@729.6,313.54 ; v2(1496.11,669.1) 1520.07,645.14 1583.49,645.14 R7.1@1601.77,626.86
  L3_SIGNAL 1 w6: v2(728.65,313.54) 747.36,294.83 747.36,216.33 783.37,180.32 865.93,180.32 1048.4,-2.15 1329.23,-2.15 1399.59,-72.51 1506.83,-72.51 1519.49,-59.86 1519.49,-20.13 1551.94,12.33 1551.94,30.33 1531.25,51.03 1531.25,151.05 1498.81,183.49 1498.81,476.14 1496.11,478.85 v2(1496.11,669.1)
  Bottom Layer w6: v2(728.65,313.54) 711.36,313.54 702.25,304.44 702.25,261.6 735.5,228.36 735.5,213.03 768.07,180.45 899.48,180.45 910.7,169.24 921.22,169.24 993.36,97.1 J6.7@993.36,34.94
SPI_MISO1: J6.12 R12.2 U13.1 | length 2122.8
  Top Layer w6: v2(604.68,321.35) 613.8,312.23 U13.1@633.26,312.23 ; v2(1496.92,714.39) 1569.73,714.39 1577.09,707.02 R12.2@1601.77,707.02
  L3_SIGNAL 1 w6: v2(604.68,321.35) 604.68,300.57 582.43,278.33 582.43,215 620.25,177.18 655.81,177.18 723.69,109.31 759.28,109.31 808.96,59.62 808.96,47.72 856.54,0.13 899.43,0.13 936.96,-37.4 936.96,-48.98 945.64,-57.66 987.82,-57.66 1048.02,-117.86 v2(1048.02,-119.32)
  L4_SIGNAL 2 w6: v2(1048.02,-119.32) 1077.71,-89.63 1189.5,-89.63 1216.37,-62.75 1306.08,-62.75 1345.13,-23.71 1345.13,29.18 1494.66,178.71 1494.66,263.19 1512.29,280.82 1512.29,546.44 1473.02,585.71 1473.02,691.19 1496.22,714.39 v2(1496.92,714.39)
  Bottom Layer w6: J6.12@1032.73,-190.65 1032.73,-134.61 v2(1048.02,-119.32)
SPI_MOSI1: J6.11 R11.1 U13.4 | length 1958.3
  Top Layer w6: v2(603.42,264.98) U13.4@631.29,264.98 ; v2(1527.06,679.55) 1589.16,679.55 R11.1@1601.77,666.94
  L3_SIGNAL 1 w6: v2(603.42,264.98) 603.42,245.73 596.8,239.11 596.8,216.19 624.8,188.18 660.37,188.18 728.24,120.31 770.29,120.31 794.68,95.92 854.13,95.92 869.55,80.49 869.55,32.44 884.51,17.48 903.27,17.48 v2(957.67,-36.92)
  L6_SIGNAL 4 w6: v4(1181.04,351.26) 1188.77,343.52 1236.03,343.52 1246.58,354.07 1246.58,424.76 1279.05,457.23 1279.05,638.24 1266.1,651.19 1266.1,670.16 1326.17,730.24 1433.33,730.24 1469.42,694.15 1512.46,694.15 v2(1527.06,679.55)
  Bottom Layer w6: v2(957.67,-36.92) 970.79,-50.04 1012.83,-50.04 1032.73,-30.14 J6.11@1032.73,34.94 1032.73,88.4 1048.56,104.23 1048.56,179.39 1040.86,187.09 1040.86,229.5 1081.97,270.61 1162.55,270.61 1187.19,295.26 1187.19,330.88 1181.04,337.04 v4(1181.04,351.26)
SW0: L4.2 R173.2 U4.10 | length 127.9
  Top Layer w10: 968.83,216.36 980.64,228.17 U4.10@980.64,265.51
  Top Layer w12: 942.53,153.4 968.83,179.7 968.83,216.36
SW0_CAP: C54.1 R173.1 | length 31.9
  Top Layer w8: C54.1@826.82,178.5 830.57,182.25 848.5,182.25 R173.1@854.61,188.35
SW1: L5.2 R175.2 U4.12 | length 131
  Top Layer w10: 1020.01,229.01 U4.12@1020.01,265.51
  Top Layer w12: 1020.01,229.01 1030.18,218.85 1030.18,217.59 1031.54,216.23 ; 1038,174.34 1038,169.55 1054.73,152.83 1058.7,152.83
  Top Layer w14: 1031.54,216.23 1031.54,180.8 1038,174.34
SW1_CAP: C55.1 R175.1 | length 35
  Top Layer w10.3: R175.1@1198.41,154.63 1211.29,141.75 C55.1@1211.29,125
SW2: L6.2 R178.2 U4.25 | length 128.7
  Top Layer w10: U4.25@980.64,386.77 980.64,424.12
  Top Layer w14: 941.96,499.45 968.83,472.58 968.83,435.93 980.64,424.12
SW2_CAP: C56.1 R178.1
SW3: L8.2 R183.2 U4.23 | length 179.9
  Top Layer w10: U4.23@1020.01,386.77 1020.01,423.23 1031.83,435.04
  Top Layer w12: 1031.83,435.04 1031.83,472.58 1058.7,499.45
  Top Layer w15: 1058.7,499.45 1064.7,499.45 L8.2@1109.9,499.45
SW3_CAP: C60.1 R183.1 | length 27.5
  Top Layer w10: C60.1@1148.43,442.7 R183.1@1148.43,470.23
TX1: U1.B4 | length 820.5
  Top Layer w7.79: U1.B4@1279.72,1383.2 1524.9,1383.2 ccw(c1524.9,1483.2) 1595.61,1412.49 ccw(c1518.88,1489.22) 1627.4,1489.22 1627.4,1597.01 ccw(c1571.48,1597.01) 1611.02,1636.55 ccw(c1576.8,1602.34) 1576.8,1650.73 ccw(c1576.8,1590.38) 1534.13,1633.05 1507.64,1606.56 cw(c1478.35,1635.84) 1478.35,1594.43 cw(c1478.35,1634.75) 1449.84,1606.24 cw(c1473.81,1630.21) 1439.91,1630.21 1439.91,1676.4
TX2: U1.B6 | length 820.5
  Top Layer w7.79: U1.B6@1279.72,1332.02 1589.93,1332.02 ccw(c1589.93,1420.4) 1652.42,1357.9 ; 1636.76,1774.83 1636.76,1734.92 ccw(c1671.2,1734.92) 1646.84,1710.57 1659.37,1698.04 cw(c1595.53,1634.19) 1685.82,1634.19 1685.82,1438.53 cw(c1571.8,1438.53) 1652.42,1357.9 ; 1652.47,1357.94 cw(c1575.03,1435.29) 1652.42,1357.9
TX3: U1.B8 | length 820.6
  Top Layer w7.79: U1.B8@1279.52,1281.05 1279.72,1280.84 1566.14,1280.84 1583.77,1280.84 ccw(c1583.77,1449.35) 1702.92,1330.19 1721.82,1349.09 ccw(c1451.93,1618.97) 1833.61,1618.97 1833.61,1676.4
USB_5V: C86.2 J5.1 L9.1
USB_AR_RS232RX: R98.1 U15.4 | length 670.1
  Top Layer w6: R98.1@1582.03,13.91 1589.45,6.5 1589.45,-2.76 v2(1600.18,-13.49) ; v2(1816.73,353.05) 1828.83,340.94 1847.17,340.94 1853.23,334.88 U15.4@1853.23,328.21
  L6_SIGNAL 4 w6: v2(1600.18,-13.49) 1556.53,30.15 1552.12,30.15 1533.61,48.66 1533.61,66.05 1549.43,81.87 1568.91,81.87 1607.27,120.22 1607.27,158.71 1629.66,181.11 1629.66,254.63 1650.09,275.05 1650.09,287.32 1671.67,308.9 1721.29,308.9 1765.44,353.05 v2(1816.73,353.05)
USB_AR_RS232TX: R97.2 U15.2 | length 684
  Top Layer w6: v2(1557.47,61.35) 1563.71,61.35 R97.2@1582.03,43.03 ; v2(1866.74,391.85) 1866.74,390.67 1891.3,366.11 1891.3,329.52 U15.2@1892.6,328.21
  L6_SIGNAL 4 w6: v2(1557.47,61.35) 1575.27,61.35 1593.82,79.9 1593.82,89.81 1634.84,130.82 1709.2,130.82 1734.5,156.12 1734.5,200.7 1717.74,217.46 1717.74,266.64 1783.94,332.85 1853.95,332.85 1878.84,357.74 1878.84,379.75 v2(1866.74,391.85)
USB_DM: J5.2 R92.2 | length 63
  Top Layer w12: R92.2@1948.97,-108.48 1973.04,-132.55 J5.2@2001.97,-132.55
USB_DP: J5.3 R91.2 | length 63.4
  Top Layer w12: R91.2@1948.97,-81.82 1951.46,-81.82 1976.6,-106.96 J5.3@2001.97,-106.96
VBUS: R90.2 R95.2 U14.8 | length 90.2
  Top Layer w9.42: U14.8@1765.34,43.03 1765.34,75.12 1750.79,89.67 R95.2@1750.79,99.82 R90.2@1778.21,99.82
VCC_3V3: C36.2 C38.2 C41.2 C43.1 C52.2 C57.2 C58.2 C59.2 C63.2 C65.2 C69.1 J1.4 J1.6 J2.52 J2.54 L11.2 L12.1 R2.2 R14.2 R43.2 R44.2 R49.2 R50.1 R52.2 R53.2 R54.2 R70.1 R83.1 R88.2 R94.1 R104.2 R105.2 R106.2 R107.2 R112.1 R115.1 R123.1 R138.1 R139.2 R142.2 R145.1 R157.2 R161.2 R165.2 R172.2 R191.1 R213.2 TP9.1 U3.5 U5.5 U6.6 U7.6 U8.6 U9.1 U10.6 U11.8 U12.5 U13.14 U17.5 | length 5770.2
  Top Layer w6.69: v2(470.39,1015.57) 495.96,1041.14 U17.5@537.82,1041.14
  Top Layer w8: U13.14@670.66,335.85 670.66,383.24 C43.1@682.22,394.8 v2(713.13,394.8)
  Top Layer w9: v2(1229.39,301.32) 1229.39,310.86 C57.2@1241.41,322.88 1263.99,345.45 U6.6@1263.99,374.27 1263.99,413.54 1256.27,421.26 1256.27,438.2 1298.42,480.34 1314.98,480.34 v2(1328.18,493.54)
  Top Layer w10: R165.2@537.82,978.07 537.82,939.59 R50.1@553.88,923.53 555.61,925.26 v2(597.7,925.26)
  Top Layer w10.73: R123.1@633.25,1016.99 634.6,1016.99 649.03,1031.42 C52.2@649.03,1042.72 649.03,1055.08 638.82,1065.29 R138.1@633.25,1065.29 635.83,1067.88 v2(635.83,1081.9)
  Top Layer w12: v2(304.69,1378.58) R213.2@319.32,1363.94
  Top Layer w15: U12.5@114.6,205.08 v2(159.42,205.08) ; v2(200.46,413.05) U5.5@243.74,413.05 ; R83.1@559.05,96.34 557.11,98.29 557.11,113.85 v2(525.95,145) 536.69,155.74 644.68,155.74 R172.2@646.25,154.18 ; v2(585.46,418.02) 615.64,418.02 633.67,436.04 R88.2@638.24,436.04 640.98,436.04 C43.1@682.22,394.8 ; R2.2@1214.31,525.25 1214.31,526.48 v2(1236.22,548.39) ; v5(1286.1,661.88) R94.1@1303.87,644.11
  Top Layer w19.68: v2(1956.87,150.7) L11.2@1956.87,111.24 TP9.1@2015.61,111.24
  Top Layer w20: v2(378.7,1027.33) 393.13,1027.33 R44.2@418.88,1001.57
  L3_SIGNAL 1 w15: v2(493.39,231.71) 496.85,228.25 496.85,174.11 v2(525.95,145)
  L3_SIGNAL 1 w20: v2(1236.22,548.39) 1273.33,548.39 v2(1328.18,493.54) ; v2(1292.25,119.95) 1385.48,119.95 1487.9,17.53 v2(1487.9,-45.52)
  L5_SIGNAL 3 w20: v2(1956.87,150.7) 1983.52,177.36 1983.52,263.65 1951.33,295.84 1922.78,295.84 1902.71,315.92 1902.71,343.18 1976.48,416.95 v2(1976.48,505.54) v2(1976.48,534.53)
  Bottom Layer w8: R14.2@1301.47,505.12 1313.05,493.54 v2(1328.18,493.54)
  Bottom Layer w9: v2(776.27,604.7) 790.04,590.93 U8.6@809.52,590.93 826.62,590.93 834.38,598.69
  Bottom Layer w9.84: 585.27,1662.34 592.84,1654.77 U7.6@625.74,1654.77
  Bottom Layer w10: U10.6@849.96,1157.77 849.96,1137.84 857.81,1130
  Bottom Layer w12: R53.2@768.74,821.11 783.1,806.76 892.22,806.76 900.11,814.65 900.11,817.33 915.76,832.97 v2(915.76,852.52) 942.33,852.52 R54.2@943.74,851.12 ; 834.38,598.69 834.38,627.36 C59.2@830,631.74 829.62,632.13 R52.2@829.62,671.77 848.19,690.34 v2(871.68,690.34) 875.77,690.34 C36.2@900,666.11 915.74,681.86 U3.5@915.74,712.3
  Bottom Layer w15: v2(159.42,205.08) C41.2@191.46,205.08 ; v2(200.46,413.05) 219.23,413.05 C38.2@223.71,408.58 ; v2(325.17,1528.43) 328.15,1525.46 R105.2@359.16,1525.46 ; v2(327.89,1653.12) R112.1@359.16,1653.12 ; R105.2@359.16,1528.43 R104.2@359.16,1558.68 R104.2@359.16,1558.88 ; R70.1@430.92,251.6 474.26,251.6 493.39,232.47 v2(493.39,231.71) ; 585.27,1662.34 565.06,1682.55 C58.2@565.06,1700.76 565.87,1701.58 v5(596.51,1701.58) ; R115.1@636.16,715.38 637.69,715.38 v2(668.74,746.43) 705.94,746.43 723.72,764.21 723.72,788.87 v2(740.28,805.43) 745.58,805.43 761.26,821.11 R53.2@768.74,821.11 ; R107.2@693.69,336.97 713.13,356.41 v2(713.13,394.8) ; v2(858,1526.43) 920.7,1526.43 960.67,1486.45 960.67,1467.64 955.18,1462.15 R139.2@955.18,1436.29 955.18,1434.84 978.74,1411.28 978.74,1342.37 R142.2@984.69,1336.43
  Bottom Layer w18: v2(773.97,1432.58) 795.21,1432.58 R145.1@798.74,1436.12
  Bottom Layer w20: v5(382,2023.43) 382,2142.43 406,2166.43 480,2166.43 494.68,2151.74 ; v5(454.51,2024) 454.51,2051.62 R157.2@455.32,2052.43 ; U11.8@567.72,2126.43 C65.2@494.69,2126.43 494.68,2151.74 ; v4@832.91,57.26 v4@843.76,57.26 ; v4(843.76,77.84) v4@843.76,57.26 ; v4(851.55,57.26) v4@843.76,57.26 ; 857.81,1130 879.06,1108.75 879.06,1100.48 908.42,1071.11 v2(908.42,1044.84) ; R161.2@889.69,2016.43 889.68,2109.37 832.63,2166.43 509.37,2166.43 494.68,2151.74 ; v2(1236.22,548.39) 1236.22,560.74 1286.1,610.61 v5(1286.1,661.88) ; v2(1487.9,-45.52) 1514.1,-45.52 1541.5,-18.12 1541.5,-7.37 1562.57,13.71 1611.44,13.71 1627.38,-2.22 1627.38,-61.31 1694.6,-128.53 1846.67,-128.53 1877.67,-159.53 1926.3,-159.53 1947.6,-138.23 1947.6,141.44 v2(1956.87,150.7)
  other v2: 526.61,350.45 557.55,361.58 487.04,444.21 553.1,448.22 572.24,490.93
  other v4: 832.88,57.29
